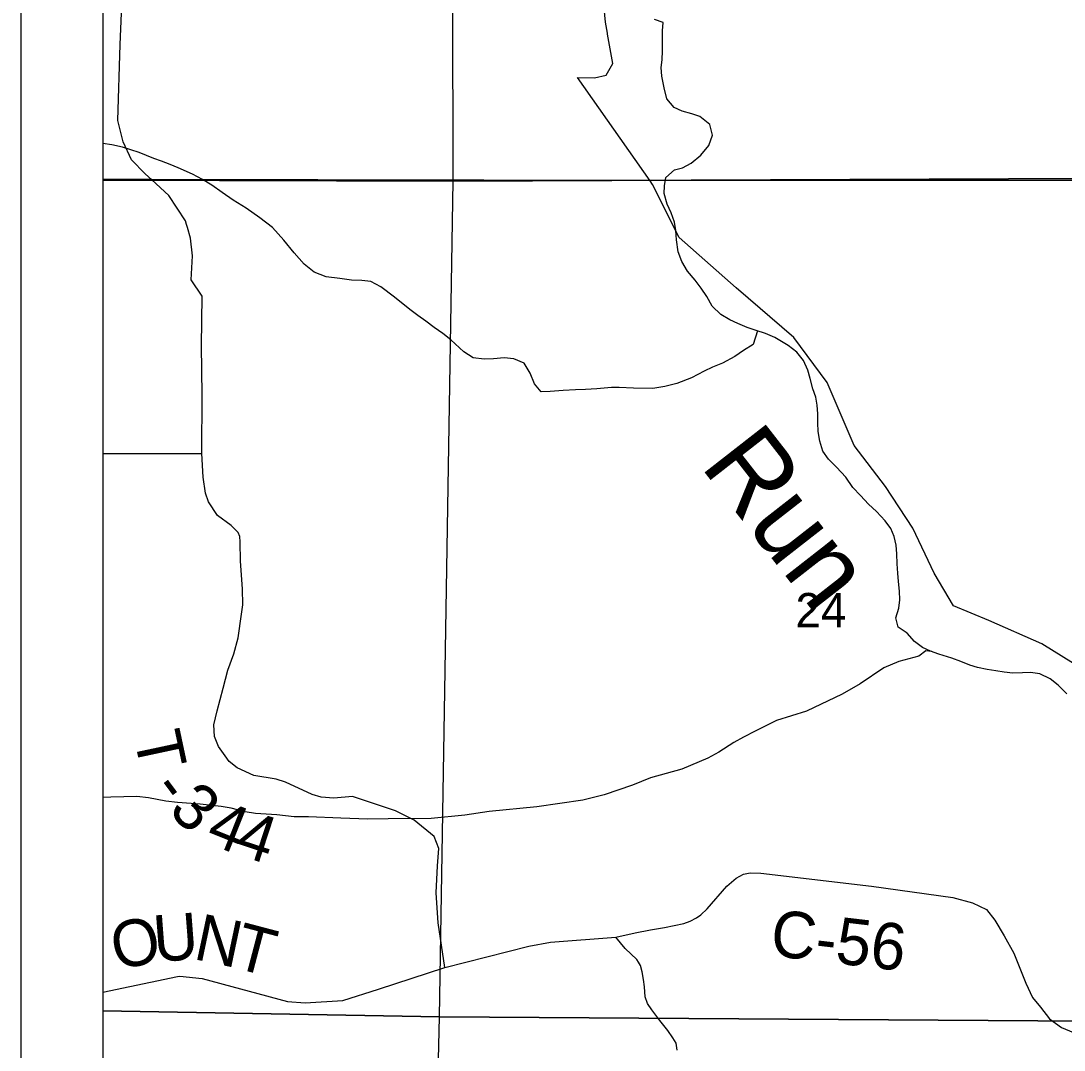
# Model space of a CAD drawing. Extents: x 0 to 34, y 0 to 22.
# Drawn here: x 2 to 3.273, y 18.088 to 19.343 of the extents above; entities that cross this region are included whole.
import ezdxf

# ---------------------------------------------------------------- set-up
doc = ezdxf.new("R2010")
doc.units = 0
for name, color, linetype in [('Default', 7, 'Continuous'), ('GM_X_County_Road', 7, 'Continuous'), ('GM_X_County_Road_Text', 7, 'Continuous'), ('GM_X_Minor_River', 7, 'Continuous'), ('GM_X_Minor_River_Text', 7, 'Continuous'), ('GM_X_Section', 7, 'Continuous'), ('GM_X_Section_Text', 7, 'Continuous'), ('GM_X_Township_Road', 7, 'Continuous'), ('GM_X_Township_Road_Text', 7, 'Continuous'), ('SH_Cut_Line', 7, 'Continuous'), ('SH_Data', 7, 'Continuous')]:
    doc.layers.add(name, color=color, linetype=linetype)

msp = doc.modelspace()

# ---------------------------------------------------------------- linework, layer by layer
at = {"layer": 'Default'}
for p, q in [((2.1, 20.9), (2.1, 19.1502)), ((2.1, 20.144), (2.1, 19.1493)), ((2.5274, 19.148), (2.526, 20.1453)), ((2.1, 19.1502), (2.1, 14.1)), ((2.1596, 19.1501), (2.1, 19.1502)), ((2.1, 19.1502), (2.1596, 19.1501)), ((2.1, 19.1493), (2.5274, 19.148)), ((2.1, 19.1493), (2.1, 18.1363)), ((2.5274, 19.148), (2.1, 19.1493)), ((2.7675, 19.1488), (2.1596, 19.1501)), ((2.1596, 19.1501), (2.7675, 19.1488)), ((2.5107, 18.1291), (2.5274, 19.148)), ((3.624, 19.1497), (2.7675, 19.1488)), ((2.7675, 19.1488), (3.624, 19.1497)), ((2.1, 18.1363), (2.1, 17.1299)), ((2.5107, 18.1291), (2.1, 18.1363)), ((2.1, 18.1363), (2.5107, 18.1291)), ((2.4891, 17.1265), (2.5107, 18.1291))]:
    msp.add_line(p, q, dxfattribs=at)
at = {"layer": 'GM_X_County_Road'}
for p, q in [((2.8615, 18.2883), (2.8727, 18.2981)), ((2.8727, 18.2981), (2.8818, 18.303)), ((2.8818, 18.303), (2.8897, 18.3045)), ((2.8897, 18.3045), (2.9028, 18.3041)), ((2.9028, 18.3041), (3.0381, 18.2883)), ((2.8373, 18.2606), (2.8615, 18.2883)), ((3.0381, 18.2883), (3.137, 18.2744)), ((3.137, 18.2744), (3.1612, 18.2679)), ((3.1612, 18.2679), (3.1783, 18.2599)), ((2.8297, 18.2532), (2.8373, 18.2606)), ((3.1783, 18.2599), (3.1883, 18.2467)), ((2.7854, 18.2378), (2.8091, 18.2429)), ((2.8091, 18.2429), (2.8165, 18.2456)), ((2.8165, 18.2456), (2.8244, 18.2496)), ((2.8244, 18.2496), (2.8297, 18.2532)), ((3.1883, 18.2467), (3.1998, 18.2278)), ((2.7258, 18.2259), (2.7494, 18.2313)), ((2.7494, 18.2313), (2.7683, 18.235)), ((2.7683, 18.235), (2.7854, 18.2378)), ((2.6199, 18.215), (2.6464, 18.2198)), ((2.6464, 18.2198), (2.7258, 18.2259)), ((3.1998, 18.2278), (3.2115, 18.2065)), ((2.5172, 18.189), (2.6199, 18.215)), ((3.2115, 18.2065), (3.2264, 18.1699)), ((2.1, 18.159), (2.1911, 18.1781)), ((2.1911, 18.1781), (2.194, 18.1787)), ((2.194, 18.1787), (2.2211, 18.1758)), ((2.4363, 18.1625), (2.5172, 18.189)), ((2.2211, 18.1758), (2.3254, 18.1476)), ((3.2264, 18.1699), (3.2343, 18.1527)), ((2.3928, 18.1488), (2.4363, 18.1625)), ((3.2343, 18.1527), (3.2442, 18.1407)), ((2.3254, 18.1476), (2.3467, 18.146)), ((2.3467, 18.146), (2.3928, 18.1488)), ((3.2442, 18.1407), (3.255, 18.1266)), ((3.255, 18.1266), (3.2697, 18.1161)), ((3.2697, 18.1161), (3.2843, 18.11))]:
    msp.add_line(p, q, dxfattribs=at)
at = {"layer": 'GM_X_Minor_River'}
for p, q in [((2.7838, 19.3416), (2.7731, 19.345)), ((2.783, 19.3313), (2.7838, 19.3416)), ((2.783, 19.3069), (2.783, 19.3313)), ((2.7826, 19.2959), (2.783, 19.3069)), ((2.7814, 19.2864), (2.7826, 19.2959)), ((2.7821, 19.2761), (2.7814, 19.2864)), ((2.7848, 19.2618), (2.7821, 19.2761)), ((2.7883, 19.2482), (2.7848, 19.2618)), ((2.7973, 19.2378), (2.7883, 19.2482)), ((2.807, 19.2335), (2.7973, 19.2378)), ((2.8185, 19.2301), (2.807, 19.2335)), ((2.8285, 19.2266), (2.8185, 19.2301)), ((2.8406, 19.2171), (2.8285, 19.2266)), ((2.844, 19.2039), (2.8406, 19.2171)), ((2.8395, 19.1916), (2.844, 19.2039)), ((2.111, 19.1924), (2.1, 19.194)), ((2.124, 19.1893), (2.111, 19.1924)), ((2.1444, 19.1828), (2.124, 19.1893)), ((2.8296, 19.1795), (2.8395, 19.1916)), ((2.1621, 19.1757), (2.1444, 19.1828)), ((2.1717, 19.1722), (2.1621, 19.1757)), ((2.1821, 19.1683), (2.1717, 19.1722)), ((2.8177, 19.17), (2.8296, 19.1795)), ((2.1921, 19.1641), (2.1821, 19.1683)), ((2.2095, 19.1563), (2.1921, 19.1641)), ((2.7871, 19.1523), (2.7974, 19.1618)), ((2.7974, 19.1618), (2.8072, 19.1643)), ((2.8072, 19.1643), (2.8177, 19.17)), ((2.2218, 19.1498), (2.2095, 19.1563)), ((2.2331, 19.1429), (2.2218, 19.1498)), ((2.7855, 19.1424), (2.7871, 19.1523)), ((2.2455, 19.1342), (2.2331, 19.1429)), ((2.2591, 19.1247), (2.2455, 19.1342)), ((2.785, 19.1328), (2.7855, 19.1424)), ((2.7885, 19.12), (2.785, 19.1328)), ((2.275, 19.115), (2.2591, 19.1247)), ((2.7934, 19.1095), (2.7885, 19.12)), ((2.2917, 19.1033), (2.275, 19.115)), ((2.7975, 19.0979), (2.7934, 19.1095)), ((2.3069, 19.0913), (2.2917, 19.1033)), ((2.799, 19.0876), (2.7975, 19.0979)), ((2.3207, 19.0761), (2.3069, 19.0913)), ((2.8001, 19.0763), (2.799, 19.0876)), ((2.3334, 19.0605), (2.3207, 19.0761)), ((2.8021, 19.0619), (2.8001, 19.0763)), ((2.3456, 19.0468), (2.3334, 19.0605)), ((2.8066, 19.0499), (2.8021, 19.0619)), ((2.3577, 19.0369), (2.3456, 19.0468)), ((2.8135, 19.0383), (2.8066, 19.0499)), ((2.3727, 19.0313), (2.3577, 19.0369)), ((2.3891, 19.0292), (2.3727, 19.0313)), ((2.8226, 19.0272), (2.8135, 19.0383)), ((2.4036, 19.0274), (2.3891, 19.0292)), ((2.4162, 19.027), (2.4036, 19.0274)), ((2.4272, 19.0254), (2.4162, 19.027)), ((2.4392, 19.019), (2.4272, 19.0254)), ((2.456, 19.0066), (2.4392, 19.019)), ((2.8301, 19.0175), (2.8226, 19.0272)), ((2.4747, 18.9916), (2.456, 19.0066)), ((2.8369, 19.0074), (2.8301, 19.0175)), ((2.8437, 18.9955), (2.8369, 19.0074)), ((2.8539, 18.9852), (2.8437, 18.9955)), ((2.4844, 18.9842), (2.4747, 18.9916)), ((2.4941, 18.9773), (2.4844, 18.9842)), ((2.8651, 18.979), (2.8539, 18.9852)), ((2.5042, 18.9697), (2.4941, 18.9773)), ((2.5148, 18.962), (2.5042, 18.9697)), ((2.8748, 18.9744), (2.8651, 18.979)), ((2.8863, 18.9694), (2.8748, 18.9744)), ((2.8971, 18.966), (2.8863, 18.9694)), ((2.5245, 18.9543), (2.5148, 18.962)), ((2.5405, 18.94), (2.5245, 18.9543)), ((2.899, 18.9654), (2.8934, 18.9487)), ((2.9086, 18.9621), (2.8971, 18.966)), ((2.9198, 18.9572), (2.9086, 18.9621)), ((2.9364, 18.9474), (2.9198, 18.9572)), ((2.8934, 18.9487), (2.8819, 18.9415)), ((2.947, 18.9394), (2.9364, 18.9474)), ((2.5518, 18.9327), (2.5405, 18.94)), ((2.5651, 18.9309), (2.5518, 18.9327)), ((2.5765, 18.9312), (2.5651, 18.9309)), ((2.5898, 18.9324), (2.5765, 18.9312)), ((2.6013, 18.9312), (2.5898, 18.9324)), ((2.614, 18.9259), (2.6013, 18.9312)), ((2.8711, 18.934), (2.8561, 18.9259)), ((2.8819, 18.9415), (2.8711, 18.934)), ((2.9549, 18.9294), (2.947, 18.9394)), ((2.9602, 18.9174), (2.9549, 18.9294)), ((2.6216, 18.914), (2.614, 18.9259)), ((2.8441, 18.921), (2.8336, 18.9161)), ((2.8561, 18.9259), (2.8441, 18.921)), ((2.9632, 18.9072), (2.9602, 18.9174)), ((2.6269, 18.9009), (2.6216, 18.914)), ((2.8183, 18.908), (2.8003, 18.9013)), ((2.8336, 18.9161), (2.8183, 18.908)), ((2.9662, 18.8947), (2.9632, 18.9072)), ((2.6348, 18.8912), (2.6269, 18.9009)), ((2.6458, 18.8916), (2.6348, 18.8912)), ((2.6618, 18.8928), (2.6458, 18.8916)), ((2.6766, 18.8933), (2.6618, 18.8928)), ((2.6891, 18.8941), (2.6766, 18.8933)), ((2.7028, 18.8949), (2.6891, 18.8941)), ((2.7206, 18.8962), (2.7028, 18.8949)), ((2.7301, 18.8965), (2.7206, 18.8962)), ((2.7476, 18.8955), (2.7301, 18.8965)), ((2.7712, 18.8951), (2.7476, 18.8955)), ((2.7856, 18.8974), (2.7712, 18.8951)), ((2.8003, 18.9013), (2.7856, 18.8974)), ((2.97, 18.8846), (2.9662, 18.8947)), ((2.9718, 18.8747), (2.97, 18.8846)), ((2.9725, 18.8641), (2.9718, 18.8747)), ((2.9725, 18.8531), (2.9725, 18.8641)), ((2.9728, 18.8428), (2.9725, 18.8531)), ((2.9747, 18.8307), (2.9728, 18.8428)), ((2.9785, 18.8187), (2.9747, 18.8307)), ((2.9856, 18.809), (2.9785, 18.8187)), ((2.9954, 18.799), (2.9856, 18.809)), ((3.0065, 18.7872), (2.9954, 18.799)), ((3.0152, 18.7742), (3.0065, 18.7872)), ((3.0243, 18.7646), (3.0152, 18.7742)), ((3.0341, 18.7542), (3.0243, 18.7646)), ((3.0439, 18.745), (3.0341, 18.7542)), ((3.0545, 18.7339), (3.0439, 18.745)), ((3.0616, 18.7243), (3.0545, 18.7339)), ((3.0657, 18.7145), (3.0616, 18.7243)), ((3.068, 18.7039), (3.0657, 18.7145)), ((3.0687, 18.6937), (3.068, 18.7039)), ((3.0694, 18.6812), (3.0687, 18.6937)), ((3.0702, 18.6701), (3.0694, 18.6812)), ((3.0709, 18.6599), (3.0702, 18.6701)), ((3.072, 18.6481), (3.0709, 18.6599)), ((3.0711, 18.6272), (3.0723, 18.6375)), ((3.0723, 18.6375), (3.072, 18.6481)), ((3.0677, 18.6153), (3.0711, 18.6272)), ((3.0703, 18.604), (3.0677, 18.6153)), ((3.0816, 18.5967), (3.0703, 18.604)), ((3.0903, 18.5867), (3.0816, 18.5967)), ((3.1, 18.5794), (3.0903, 18.5867)), ((3.1042, 18.5753), (3.0956, 18.5686)), ((3.11, 18.5748), (3.1, 18.5794)), ((3.1114, 18.5743), (3.1042, 18.5753)), ((3.12, 18.5713), (3.11, 18.5748)), ((3.0711, 18.5622), (3.0528, 18.5543)), ((3.0956, 18.5686), (3.0711, 18.5622)), ((3.1358, 18.5661), (3.12, 18.5713)), ((3.1469, 18.5622), (3.1358, 18.5661)), ((3.1577, 18.5576), (3.1469, 18.5622)), ((3.0528, 18.5543), (3.024, 18.5348)), ((3.1673, 18.5549), (3.1577, 18.5576)), ((3.1791, 18.5526), (3.1673, 18.5549)), ((3.1898, 18.551), (3.1791, 18.5526)), ((3.1998, 18.5494), (3.1898, 18.551)), ((3.2105, 18.5479), (3.1998, 18.5494)), ((3.2222, 18.5486), (3.2105, 18.5479)), ((3.2321, 18.5489), (3.2222, 18.5486)), ((3.2432, 18.547), (3.2321, 18.5489)), ((3.2559, 18.5409), (3.2432, 18.547)), ((3.024, 18.5348), (3.0023, 18.5222)), ((3.2657, 18.5332), (3.2559, 18.5409)), ((3.0023, 18.5222), (2.9588, 18.5018)), ((3.2762, 18.5229), (3.2657, 18.5332)), ((2.9588, 18.5018), (2.922, 18.4901)), ((2.922, 18.4901), (2.8961, 18.4772)), ((2.8961, 18.4772), (2.8819, 18.4701)), ((2.8699, 18.4634), (2.8516, 18.4517)), ((2.8819, 18.4701), (2.8699, 18.4634)), ((2.8516, 18.4517), (2.8381, 18.4443)), ((2.8381, 18.4443), (2.8066, 18.4308)), ((2.7682, 18.4203), (2.7464, 18.4116)), ((2.8066, 18.4308), (2.7682, 18.4203)), ((2.7464, 18.4116), (2.7119, 18.3996)), ((2.1098, 18.3969), (2.1, 18.3965)), ((2.1415, 18.3974), (2.1098, 18.3969)), ((2.1559, 18.3961), (2.1415, 18.3974)), ((2.1768, 18.3919), (2.1559, 18.3961)), ((2.7119, 18.3996), (2.6855, 18.3931)), ((2.1912, 18.3903), (2.1768, 18.3919)), ((2.2188, 18.3881), (2.1912, 18.3903)), ((2.2442, 18.3854), (2.2188, 18.3881)), ((2.2567, 18.3834), (2.2442, 18.3854)), ((2.2738, 18.3791), (2.2567, 18.3834)), ((2.6297, 18.3849), (2.5712, 18.3794)), ((2.6855, 18.3931), (2.6297, 18.3849)), ((2.2863, 18.377), (2.2738, 18.3791)), ((2.3124, 18.3751), (2.2863, 18.377)), ((2.3336, 18.3728), (2.3124, 18.3751)), ((2.351, 18.3727), (2.3336, 18.3728)), ((2.3903, 18.3711), (2.351, 18.3727)), ((2.4232, 18.3701), (2.3903, 18.3711)), ((2.4482, 18.3702), (2.4232, 18.3701)), ((2.5007, 18.3706), (2.4482, 18.3702)), ((2.5418, 18.3747), (2.5007, 18.3706)), ((2.5712, 18.3794), (2.5418, 18.3747))]:
    msp.add_line(p, q, dxfattribs=at)
at = {"layer": 'GM_X_Section'}
for p, q in [((2.5274, 19.148), (2.526, 20.1453)), ((2.5107, 18.1291), (2.5274, 19.148)), ((3.5387, 19.1524), (2.5274, 19.148)), ((2.5274, 19.148), (3.5387, 19.1524)), ((2.4891, 17.1265), (2.5107, 18.1291)), ((3.5154, 18.1224), (2.5107, 18.1291)), ((2.5107, 18.1291), (3.5154, 18.1224))]:
    msp.add_line(p, q, dxfattribs=at)
at = {"layer": 'GM_X_Township_Road'}
for p, q in [((2.7134, 19.3418), (2.7093, 19.3837)), ((2.1212, 19.3147), (2.1237, 19.3729)), ((2.7157, 19.3285), (2.7134, 19.3418)), ((2.7159, 19.3274), (2.7157, 19.3285)), ((2.7221, 19.2916), (2.7159, 19.3274)), ((2.1182, 19.222), (2.1212, 19.3147)), ((2.714, 19.2772), (2.7221, 19.2916)), ((2.7677, 19.1483), (2.679, 19.2742)), ((2.679, 19.2742), (2.6998, 19.2739)), ((2.6998, 19.2739), (2.714, 19.2772)), ((2.125, 19.1961), (2.1182, 19.222)), ((2.135, 19.1741), (2.125, 19.1961)), ((2.1517, 19.157), (2.135, 19.1741)), ((2.1598, 19.1496), (2.1517, 19.157)), ((2.1805, 19.1306), (2.1598, 19.1496)), ((2.7708, 19.1437), (2.7677, 19.1483)), ((2.8034, 19.0792), (2.7708, 19.1437)), ((2.2007, 19.0996), (2.1805, 19.1306)), ((2.2021, 19.095), (2.2007, 19.0996)), ((2.2032, 19.0913), (2.2021, 19.095)), ((2.207, 19.0786), (2.2032, 19.0913)), ((2.2095, 19.0567), (2.207, 19.0786)), ((2.8727, 19.0177), (2.8034, 19.0792)), ((2.2077, 19.0277), (2.2095, 19.0567)), ((2.2211, 19.0079), (2.2077, 19.0277)), ((2.2202, 18.9471), (2.2211, 19.0079)), ((2.943, 18.9574), (2.8727, 19.0177)), ((2.9837, 18.9026), (2.943, 18.9574)), ((2.2211, 18.8872), (2.2202, 18.9471)), ((3.0166, 18.8258), (2.9837, 18.9026)), ((2.2208, 18.8159), (2.2211, 18.8872)), ((2.1, 18.816), (2.2208, 18.8159)), ((2.2223, 18.787), (2.2208, 18.8159)), ((3.0551, 18.7755), (3.0166, 18.8258)), ((2.2251, 18.7673), (2.2223, 18.787)), ((2.229, 18.7569), (2.2251, 18.7673)), ((3.0884, 18.7249), (3.0551, 18.7755)), ((2.2401, 18.7403), (2.229, 18.7569)), ((2.2568, 18.728), (2.2401, 18.7403)), ((2.265, 18.7195), (2.2568, 18.728)), ((2.2673, 18.7148), (2.265, 18.7195)), ((2.2677, 18.7081), (2.2673, 18.7148)), ((3.1142, 18.6699), (3.0884, 18.7249)), ((2.268, 18.6846), (2.2677, 18.7081)), ((2.2703, 18.6507), (2.268, 18.6846)), ((3.1379, 18.6303), (3.1142, 18.6699)), ((2.271, 18.6314), (2.2703, 18.6507)), ((2.2693, 18.6201), (2.271, 18.6314)), ((3.1811, 18.6124), (3.1379, 18.6303)), ((2.2652, 18.5909), (2.2693, 18.6201)), ((3.2459, 18.5838), (3.1811, 18.6124)), ((2.2597, 18.5716), (2.2652, 18.5909)), ((3.2961, 18.5526), (3.2459, 18.5838)), ((2.2526, 18.5518), (2.2597, 18.5716)), ((2.247, 18.5298), (2.2526, 18.5518)), ((2.2396, 18.5019), (2.247, 18.5298)), ((2.2356, 18.4849), (2.2396, 18.5019)), ((2.2362, 18.4709), (2.2356, 18.4849)), ((2.241, 18.4585), (2.2362, 18.4709)), ((2.2494, 18.447), (2.241, 18.4585)), ((2.2543, 18.4403), (2.2494, 18.447)), ((2.2638, 18.4325), (2.2543, 18.4403)), ((2.2841, 18.4232), (2.2638, 18.4325)), ((2.3114, 18.4186), (2.2841, 18.4232)), ((2.3227, 18.4149), (2.3114, 18.4186)), ((2.3556, 18.4), (2.3227, 18.4149)), ((2.3665, 18.3967), (2.3556, 18.4)), ((2.3819, 18.3957), (2.3665, 18.3967)), ((2.4046, 18.3976), (2.3819, 18.3957)), ((2.4571, 18.3801), (2.4046, 18.3976)), ((2.4798, 18.3688), (2.4571, 18.3801)), ((2.5044, 18.3489), (2.4798, 18.3688)), ((2.5101, 18.3342), (2.5044, 18.3489)), ((2.5082, 18.313), (2.5101, 18.3342)), ((2.5068, 18.2803), (2.5082, 18.313)), ((2.5092, 18.2434), (2.5068, 18.2803)), ((2.5172, 18.189), (2.5092, 18.2434)), ((2.7373, 18.2124), (2.7258, 18.2259)), ((2.7515, 18.1987), (2.7373, 18.2124)), ((2.7538, 18.1954), (2.7515, 18.1987)), ((2.7559, 18.1915), (2.7538, 18.1954)), ((2.7581, 18.1837), (2.7559, 18.1915)), ((2.7596, 18.1743), (2.7581, 18.1837)), ((2.7608, 18.1656), (2.7596, 18.1743)), ((2.7616, 18.1534), (2.7608, 18.1656)), ((2.7647, 18.1453), (2.7616, 18.1534)), ((2.7697, 18.1373), (2.7647, 18.1453)), ((2.7797, 18.1244), (2.7697, 18.1373)), ((2.7894, 18.1122), (2.7797, 18.1244)), ((2.7954, 18.1033), (2.7894, 18.1122)), ((2.7996, 18.0968), (2.7954, 18.1033)), ((2.8006, 18.0881), (2.7996, 18.0968))]:
    msp.add_line(p, q, dxfattribs=at)
at = {"layer": 'SH_Cut_Line'}
msp.add_line((2.1, 20.9), (2.1, 14.1), dxfattribs=at)
at = {"layer": 'SH_Data'}
for p, q in [((2, 21), (2, 14)), ((2.1, 20.9), (2.1, 14.1))]:
    msp.add_line(p, q, dxfattribs=at)

# ---------------------------------------------------------------- texts
at = {"layer": 'GM_X_County_Road_Text'}
for s, height, rotation, p in [('U', 0.0568, 4.3389, (2.1635, 18.1956)), ('C-56', 0.05682, 353.2897, (2.9128, 18.2038)), ('O', 0.0568, 12.0444, (2.1166, 18.1855)), ('N', 0.0568, 348.0121, (2.2091, 18.1997)), ('T', 0.0568, 345.2362, (2.2573, 18.1895))]:
    msp.add_text(s, height=height, rotation=rotation, dxfattribs=at).set_placement(p)
at = {"layer": 'GM_X_Minor_River_Text'}
msp.add_text('Run', height=0.09471, rotation=307.955, dxfattribs=at).set_placement((2.8279, 18.801))
at = {"layer": 'GM_X_Section_Text'}
msp.add_text('24', height=0.04186, rotation=0, dxfattribs=at).set_placement((2.9451, 18.6039))
at = {"layer": 'GM_X_Township_Road_Text'}
for s, rotation, p in [('T', 282.0454, (2.1376, 18.4712)), ('-', 306.5459, (2.1573, 18.4057)), ('3', 316.7866, (2.1785, 18.3787)), ('4', 338.2372, (2.2235, 18.3423)), ('4', 341.8844, (2.2597, 18.328))]:
    msp.add_text(s, height=0.0568, rotation=rotation, dxfattribs=at).set_placement(p)

doc.saveas('drawing.dxf')
